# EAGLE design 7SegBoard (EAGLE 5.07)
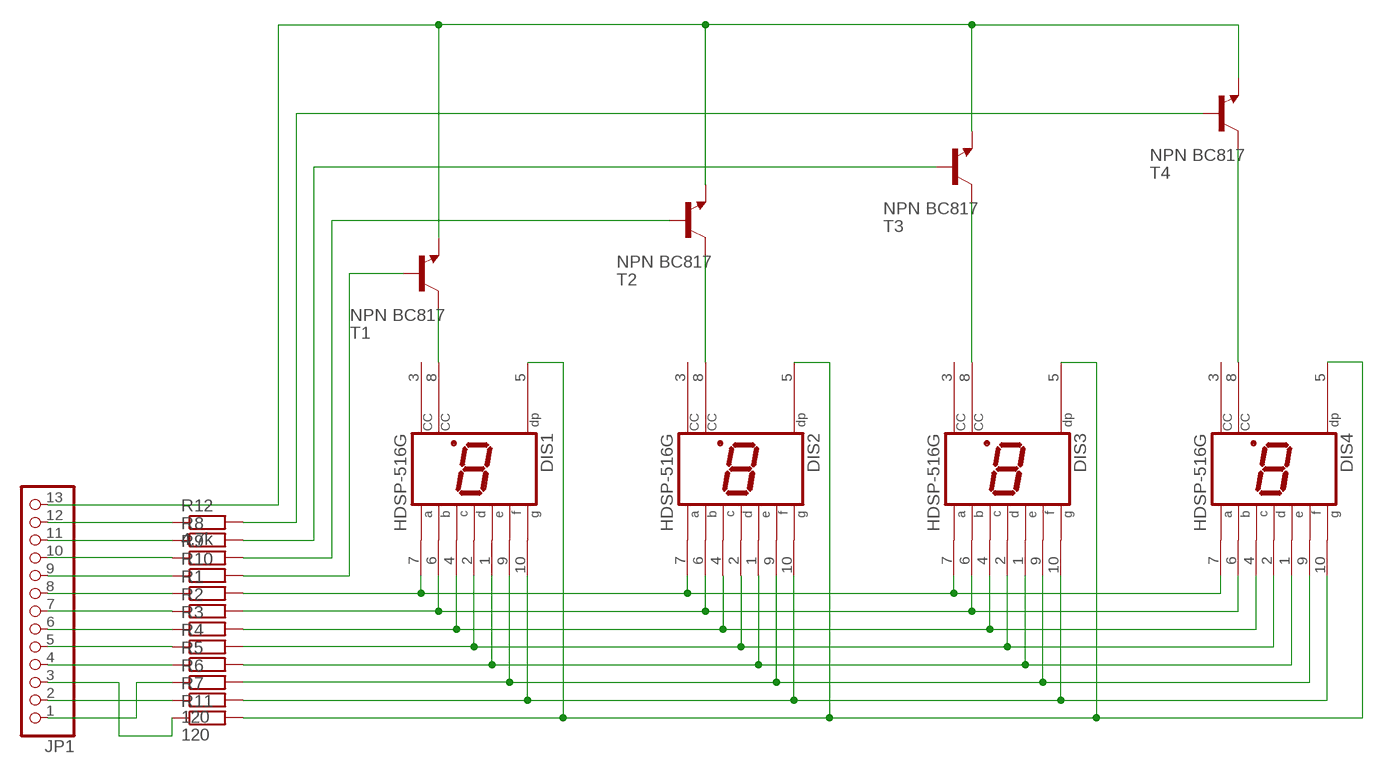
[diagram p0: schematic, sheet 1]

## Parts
DIS1  HDSP-516G  HD-H103  [HDSP-M]
DIS2  HDSP-516G  HD-H103  [HDSP-M]
DIS3  HDSP-516G  HD-H103  [HDSP-M]
DIS4  HDSP-516G  HD-H103  [HDSP-M]
JP1  PINHD-1X13  [1X13]
R1  R-EU_R0805  [R0805]
R2  R-EU_R0805  [R0805]
R3  R-EU_R0805  [R0805]
R4  R-EU_R0805  [R0805]
R5  R-EU_R0805  [R0805]
R6  R-EU_R0805  [R0805]
R7  120  R-EU_R0805  [R0805]
R8  R-EU_R1206  [R1206]
R9  R-EU_R1206  [R1206]
R10  R-EU_R0805  [R0805]
R11  120  R-EU_R0805  [R0805]
R12  4,7k  R-EU_R1206  [R1206]
T1  NPN BC817  BC817-16-NPN-SOT23-BEC  [SOT23-BEC]
T2  NPN BC817  BC817-16-NPN-SOT23-BEC  [SOT23-BEC]
T3  NPN BC817  BC817-16-NPN-SOT23-BEC  [SOT23-BEC]
T4  NPN BC817  BC817-16-NPN-SOT23-BEC  [SOT23-BEC]

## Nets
N$1: R12.2 T4.B
N$2: JP1.1 R6.1
N$3: JP1.12 R12.1
N$4: JP1.13 T1.E T2.E T3.E T4.E
N$5: JP1.3 R11.1
N$8: JP1.8 R1.1
N$9: JP1.7 R2.1
N$10: JP1.6 R3.1
N$11: JP1.5 R4.1
N$12: JP1.4 R5.1
N$14: JP1.2 R7.1
N$15: JP1.9 R10.1
N$16: JP1.10 R9.1
N$17: JP1.11 R8.1
N$18: R10.2 T1.B
N$19: DIS1.8(CC) T1.C
N$20: R9.2 T2.B
N$21: R8.2 T3.B
N$22: DIS2.8(CC) T2.C
N$23: DIS3.8(CC) T3.C
N$26: DIS1.7(A) DIS2.7(A) DIS3.7(A) DIS4.7(A) R1.2
N$27: DIS1.6(B) DIS2.6(B) DIS3.6(B) DIS4.6(B) R2.2
N$28: DIS1.4(C) DIS2.4(C) DIS3.4(C) DIS4.4(C) R3.2
N$29: DIS1.2(D) DIS2.2(D) DIS3.2(D) DIS4.2(D) R4.2
N$30: DIS1.1(E) DIS2.1(E) DIS3.1(E) DIS4.1(E) R5.2
N$31: DIS1.9(F) DIS2.9(F) DIS3.9(F) DIS4.9(F) R6.2
N$32: DIS1.10(G) DIS2.10(G) DIS3.10(G) DIS4.10(G) R7.2
N$33: DIS4.8(CC) T4.C
N$34: DIS1.5(DP) DIS2.5(DP) DIS3.5(DP) DIS4.5(DP) R11.2
Unconnected: DIS1.3(CC) DIS2.3(CC) DIS3.3(CC) DIS4.3(CC)

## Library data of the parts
DIS1-DIS4 = display-hp:HD-H103: LED DISPLAY 1-character 7 segment, decimal point right
JP1 = pinhead:PINHD-1X13: PIN HEADER
R1-R12 = rcl:R-EU_: RESISTOR, European symbol
T1-T4 = transistor:*-NPN-: NPN Transistror BF959 corrected 2008.03.06

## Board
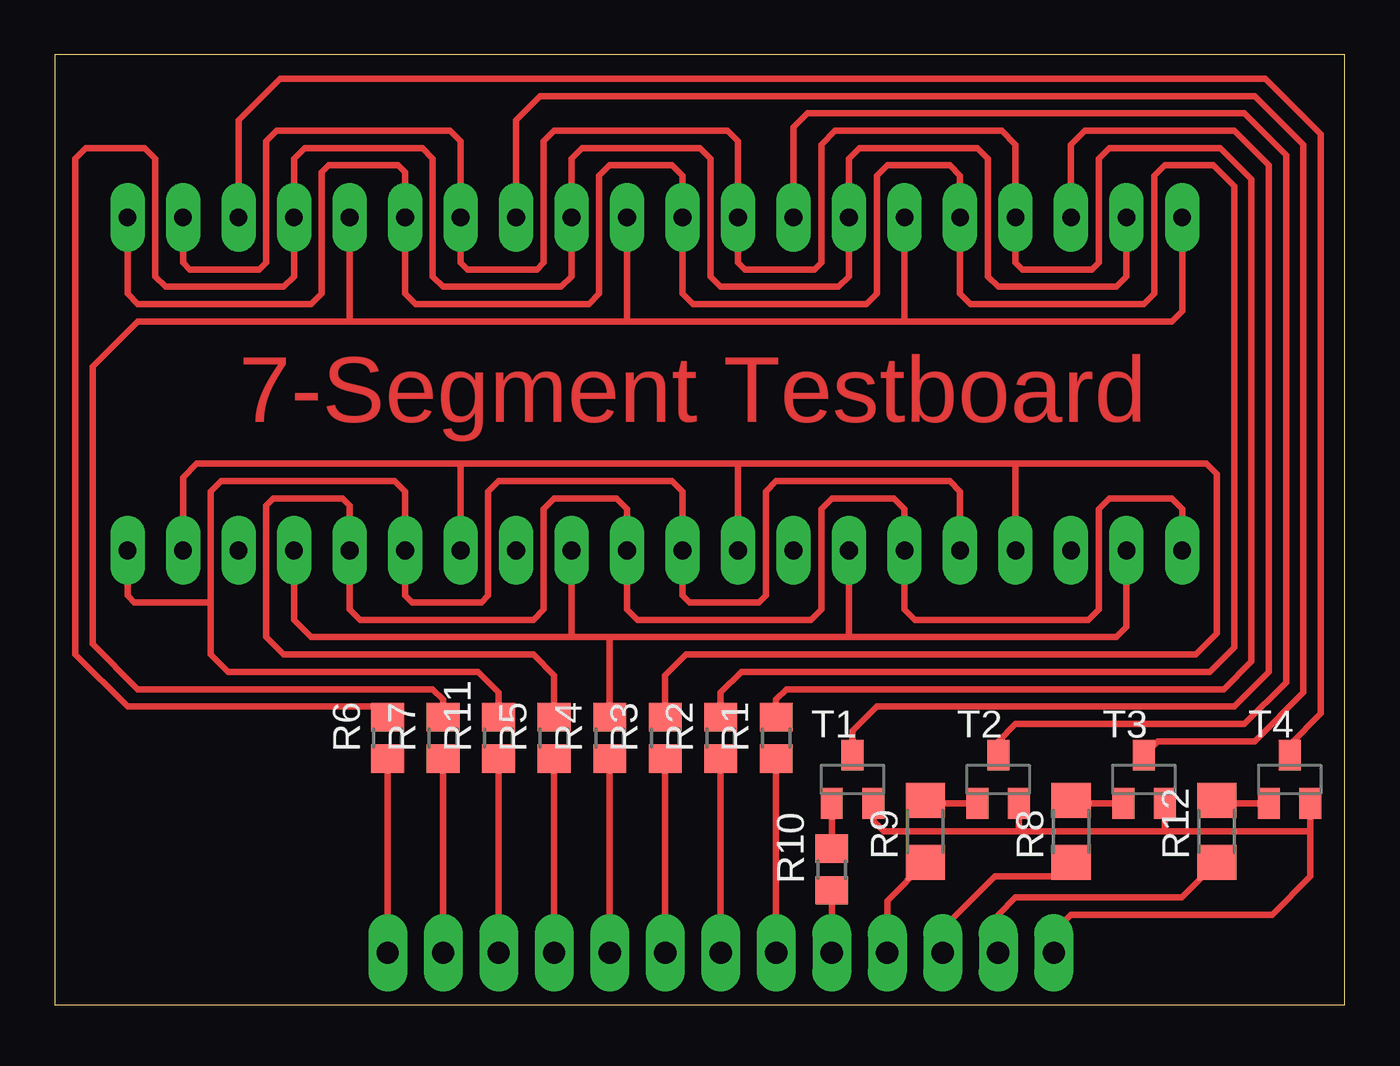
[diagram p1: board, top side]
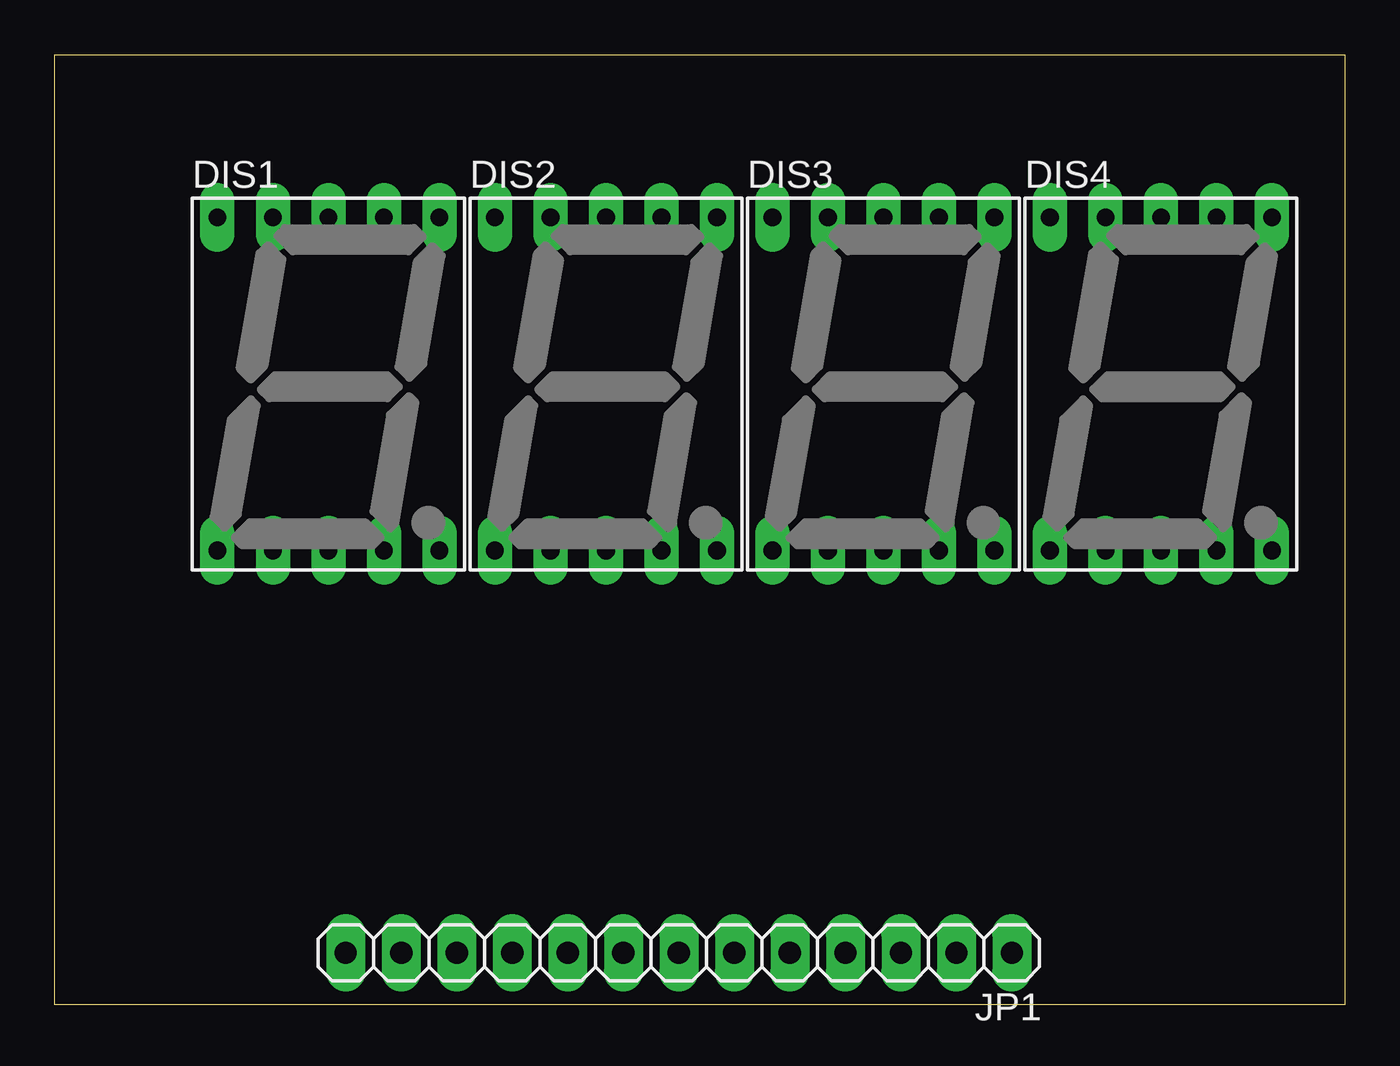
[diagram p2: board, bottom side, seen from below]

Size 59.04 x 43.49 mm. Coordinates in mm from the lower left corner, seen from the top.
Outline: 0,0 59.04,0 59.04,43.49 0,43.49 0,0
Copper layers (1*16): Top 0.035mm / dielectric 1.5mm / Bottom 0.035mm
Design rules "default *": minimum track width 10mil, minimum drill 24mil, track to track 8mil, track to pad 8mil, pad to pad 8mil, via to via 8mil, smd to smd 8mil, copper to edge 40mil, drill to drill 8mil, minimum pad ring 15mil, minimum via ring 8mil, stop-mask expansion 4mil, vias tented up to drill 0mil, thermal gap 10mil

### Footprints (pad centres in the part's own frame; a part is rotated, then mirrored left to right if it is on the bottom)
HDSP-M = drill 0.813 long: 1 -5.08,-7.62; 2 -2.54,-7.62; 3 0,-7.62; 4 2.54,-7.62; 5 5.08,-7.62; 6 5.08,7.62; 7 2.54,7.62; 8 0,7.62; 9 -2.54,7.62; 10 -5.08,7.62
1X13 = drill 1.016 long: 1 -15.24,0; 2 -12.7,0; 3 -10.16,0; 4 -7.62,0; 5 -5.08,0; 6 -2.54,0; 7 0,0; 8 2.54,0; 9 5.08,0; 10 7.62,0; 11 10.16,0; 12 12.7,0; 13 15.24,0
R0805 = smd 1.3 x 1.5: 1 -0.95,0; 2 0.95,0
R1206 = smd 1.6 x 1.803: 1 -1.422,0; 2 1.422,0
SOT23-BEC = smd 1 x 1.4: B -0.95,-1.1; C 0,1.1; E 0.95,-1.1

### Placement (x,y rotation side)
DIS1  46.51,28.42 0 bottom
DIS2  33.81,28.42 0 bottom
DIS3  21.11,28.42 0 bottom
DIS4  8.41,28.42 0 bottom
JP1  30.48,2.38 180 bottom
R1  33.02,12.22 90 top
R2  30.48,12.22 90 top
R3  27.94,12.22 90 top
R4  25.4,12.22 90 top
R5  22.86,12.22 90 top
R6  15.24,12.22 90 top
R7  17.78,12.22 90 top
R8  46.51,7.94 90 top
R9  39.85,7.94 90 top
R10  35.56,6.19 90 top
R11  20.32,12.22 90 top
R12  53.18,7.94 90 top
T1  36.51,10.32 0 top
T2  43.18,10.32 0 top
T3  49.85,10.32 0 top
T4  56.52,10.32 0 top

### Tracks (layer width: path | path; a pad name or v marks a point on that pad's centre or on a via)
N$1
  Top 0.305: T4.B 53.32,9.22 R12.2
N$2
  Top 0.305: JP1.1 R6.1 | R6.1
N$3
  Top 0.305: JP1.12 43.18,4.13 43.97,4.92 51.59,4.92 R12.1
N$4
  Top 0.305: T1.E 37.46,8.42 37.94,7.94 44.13,7.94 | 57.47,7.94 57.47,5.87 55.72,4.13 46.51,4.13 45.72,3.33 JP1.13 | 57.47,7.94 T4.E | 44.13,7.94 T2.E | 44.13,7.94 50.8,7.94 | 50.8,7.94 T3.E | 50.8,7.94 57.47,7.94
N$5
  Top 0.305: JP1.3 R11.1
N$8
  Top 0.305: JP1.8 R1.1 | R1.1
N$9
  Top 0.305: JP1.7 R2.1 | R2.1
N$10
  Top 0.305: JP1.6 R3.1 | R3.1
N$11
  Top 0.305: JP1.5 R4.1 | R4.1
N$12
  Top 0.305: JP1.4 R5.1 | R5.1
N$14
  Top 0.305: JP1.2 R7.1 | R7.1
N$15
  Top 0.305: JP1.9 R10.1
N$16
  Top 0.305: JP1.10 38.1,4.77 R9.1
N$17
  Top 0.305: JP1.11 40.64,3.49 43.02,5.87 45.87,5.87 R8.1
N$18
  Top 0.305: T1.B R10.2
N$19
  Top 0.305: DIS1.8 46.51,39.37 47.15,40.01 53.98,40.01 55.56,38.42 55.56,15.24 53.98,13.65 37.62,13.65 36.51,12.54 T1.C
N$20
  Top 0.305: T2.B 39.99,9.22 R9.2
N$21
  Top 0.305: T3.B 46.65,9.22 R8.2
N$22
  Top 0.305: DIS2.8 33.81,40.16 34.45,40.8 54.45,40.8 56.36,38.89 56.36,14.76 54.45,12.86 43.97,12.86 43.18,12.06 T2.C
N$23
  Top 0.305: DIS3.8 21.11,40.48 22.23,41.59 54.93,41.59 57.15,39.37 57.15,14.29 54.93,12.06 50.49,12.06 T3.C
N$26
  Top 0.305: DIS1.7 43.97,39.37 43.34,40.01 35.72,40.01 35.08,39.37 35.08,33.97 34.77,33.66 31.59,33.66 31.27,33.97 DIS2.7 31.27,39.53 30.8,40.01 22.86,40.01 22.38,39.53 22.38,33.97 22.07,33.66 18.89,33.66 18.57,33.97 DIS3.7 18.57,39.53 18.1,40.01 10.16,40.01 9.68,39.53 9.68,33.97 9.37,33.66 6.19,33.66 5.87,33.97 DIS4.7 | DIS1.7 | DIS1.7 43.97,33.97 44.29,33.66 47.47,33.66 47.78,33.97 47.78,38.73 48.26,39.21 53.34,39.21 54.77,37.78 54.77,15.72 53.5,14.45 33.5,14.45 33.02,13.97 R1.2 | DIS4.7
N$27
  Top 0.305: R2.2 30.48,14.29 31.43,15.24 52.86,15.24 53.98,16.35 53.98,37.47 53.02,38.42 50.8,38.42 50.32,37.94 50.32,32.54 49.85,32.07 41.91,32.07 41.43,32.54 DIS1.6 | DIS1.6 41.43,37.94 40.96,38.42 38.1,38.42 37.62,37.94 37.62,32.54 37.15,32.07 29.21,32.07 28.73,32.54 DIS2.6 28.73,37.94 28.26,38.42 25.4,38.42 24.92,37.94 24.92,32.54 24.45,32.07 16.51,32.07 16.03,32.54 DIS3.6 16.03,38.1 15.72,38.42 12.54,38.42 12.22,38.1 12.22,32.54 11.75,32.07 3.81,32.07 3.33,32.54 DIS4.6 | DIS1.6
N$28
  Top 0.305: R3.2 27.94,15.08 28.89,16.03 52.23,16.03 53.18,16.99 53.18,24.29 52.7,24.77 43.97,24.77 | 43.97,24.77 DIS1.4 | 31.27,24.77 DIS2.4 | 31.27,24.77 43.97,24.77 | 18.57,24.77 6.51,24.77 5.87,24.13 DIS4.4 | 18.57,24.77 31.27,24.77 | DIS4.4 | 18.57,24.77 DIS3.4
N$29
  Top 0.305: DIS1.2 49.05,17.3 48.58,16.83 36.35,16.83 | 36.35,16.83 DIS2.2 | 23.65,16.83 11.75,16.83 10.95,17.62 DIS4.2 | DIS4.2 | 23.65,16.83 DIS3.2 | 25.4,16.83 36.35,16.83 | 25.4,16.83 R4.2 | 23.65,16.83 25.4,16.83
N$30
  Top 0.305: DIS1.1 51.59,22.7 51.12,23.18 48.26,23.18 47.78,22.7 47.78,18.1 47.31,17.62 39.37,17.62 38.89,18.1 DIS2.1 38.89,22.7 38.42,23.18 35.56,23.18 35.08,22.7 35.08,18.1 34.61,17.62 26.67,17.62 26.19,18.1 DIS3.1 26.19,22.7 25.72,23.18 22.86,23.18 22.38,22.7 22.38,18.1 21.91,17.62 13.97,17.62 13.49,18.1 DIS4.1 | DIS1.1 | DIS4.1 13.49,22.86 13.18,23.18 10,23.18 9.68,22.86 9.68,16.83 10.48,16.03 21.91,16.03 22.86,15.08 R5.2 | DIS4.1
N$31
  Top 0.305: DIS1.9 49.05,33.34 48.58,32.86 43.18,32.86 42.7,33.34 42.7,38.73 42.23,39.21 36.83,39.21 36.35,38.73 DIS2.9 36.35,33.34 35.88,32.86 30.48,32.86 30,33.34 30,38.73 29.53,39.21 24.13,39.21 23.65,38.73 DIS3.9 23.65,33.34 23.18,32.86 17.78,32.86 17.3,33.34 17.3,38.73 16.83,39.21 11.43,39.21 10.95,38.73 DIS4.9 | DIS1.9 | DIS4.9 10.95,33.34 10.48,32.86 5.08,32.86 4.6,33.34 4.6,38.73 4.13,39.21 1.43,39.21 0.95,38.73 0.95,16.03 | DIS4.9 | R6.2 14.76,13.65 3.33,13.65 0.95,16.03 | 0.95,16.03
N$32
  Top 0.305: DIS1.10 51.59,31.75 51.12,31.27 38.89,31.27 | DIS1.10 | 26.19,31.27 DIS3.10 | 26.19,31.27 38.89,31.27 | 38.89,31.27 DIS2.10 | 13.49,31.27 26.19,31.27 | 13.49,31.27 DIS4.10 | 13.49,31.27 3.81,31.27 1.75,29.21 1.75,16.51 3.81,14.45 17.3,14.45 17.78,13.97 R7.2
N$33
  Top 0.305: DIS4.8 8.41,40.48 10.32,42.39 55.4,42.39 57.94,39.85 57.94,13.34 56.52,11.91 T4.C | DIS4.8
N$34
  Top 0.305: DIS1.5 41.43,23.5 40.96,23.97 33.02,23.97 32.54,23.5 32.54,18.73 32.23,18.41 29.05,18.41 28.73,18.73 DIS2.5 28.73,23.5 28.26,23.97 20.32,23.97 19.84,23.5 19.84,18.73 19.53,18.41 16.35,18.41 16.03,18.73 DIS3.5 16.03,23.5 15.56,23.97 7.62,23.97 7.14,23.5 7.14,18.41 | DIS4.5 3.33,18.73 3.65,18.41 7.14,18.41 | DIS4.5 | R11.2 20.32,14.29 19.37,15.24 7.94,15.24 7.14,16.03 7.14,18.26 7.14,18.41

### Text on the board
Top: 7-Segment Testboard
